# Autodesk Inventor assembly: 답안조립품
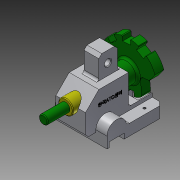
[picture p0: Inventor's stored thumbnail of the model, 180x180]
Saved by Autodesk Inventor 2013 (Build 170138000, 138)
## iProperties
Created: 2016-11
Part Number: 답안조립품
Document SubType Name: Assembly
Designer: cad22
Author: cad22
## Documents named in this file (4)
- C:\Documents and Settings\cad22\바탕 화면\461108V1011\답안조립품.iam
- C:\Documents and Settings\cad22\바탕 화면\461108V1011\1-본체.ipt
- C:\Documents and Settings\cad22\바탕 화면\461108V1011\부시.ipt
- C:\Documents and Settings\cad22\바탕 화면\461108V1011\분할축.ipt
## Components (1 placed, 1 different names)
1. 1-본체:1
